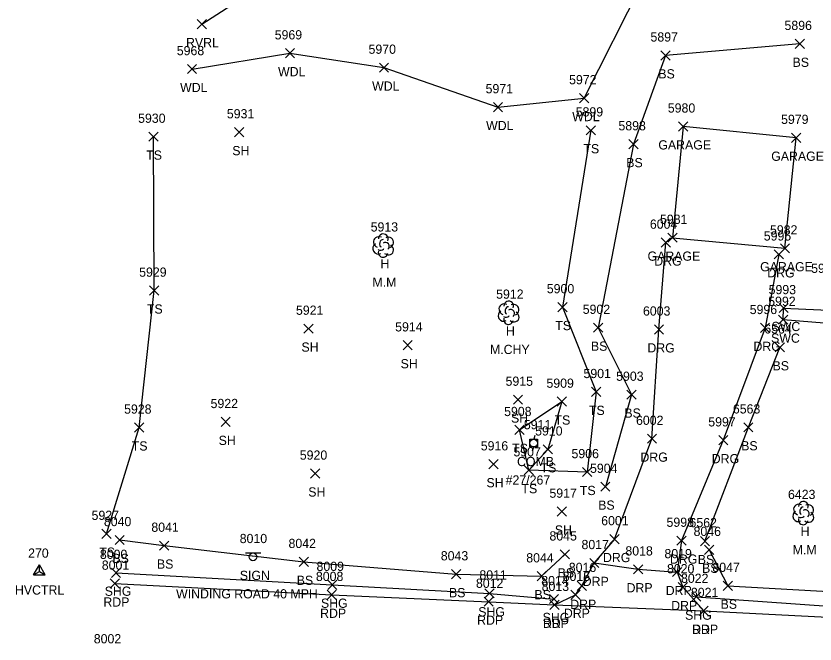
# Model space of a CAD drawing. Extents: x 1588028 to 1589597, y 137576 to 138176.
# Drawn here: x 1588400.7 to 1588574.1, y 137910.1 to 138046.3 of the extents above; entities that cross this region are included whole.
import ezdxf

# ---------------------------------------------------------------- set-up
doc = ezdxf.new("R2010")
doc.units = 0
for name, color, linetype in [('C_A', 7, 'Continuous'), ('C_I', 7, 'Continuous'), ('CPSM', 7, 'Continuous'), ('L_A', 7, 'Continuous'), ('L_C', 7, 'Continuous'), ('L_I', 7, 'Continuous'), ('L_TIC', 7, 'Continuous'), ('LAWA', 7, 'Continuous'), ('LAWE', 7, 'Continuous'), ('LBC', 7, 'Continuous'), ('LELB', 7, 'Continuous'), ('LTD', 7, 'Continuous'), ('P_A', 7, 'Continuous'), ('P_I', 7, 'Continuous'), ('P_TIC', 7, 'Continuous'), ('PET', 7, 'Continuous'), ('PSU', 7, 'Continuous'), ('R_A', 7, 'Continuous'), ('R_I', 7, 'Continuous'), ('R_TIC', 7, 'Continuous'), ('RDG', 7, 'Continuous'), ('RDP', 7, 'Continuous'), ('RSW', 7, 'Continuous'), ('S_A', 7, 'Continuous'), ('S_C', 7, 'Continuous'), ('S_I', 7, 'Continuous'), ('SSGN', 7, 'Continuous'), ('U_A', 7, 'Continuous'), ('U_C', 7, 'Continuous'), ('U_I', 7, 'Continuous'), ('UP', 7, 'Continuous')]:
    doc.layers.add(name, color=color, linetype=linetype)

msp = doc.modelspace()

# ---------------------------------------------------------------- linework, layer by layer
at = {"layer": 'CPSM'}
for p, q in [((1588404.52, 137925.06), (1588405.77, 137927.22)), ((1588407.02, 137925.06), (1588405.77, 137927.22)), ((1588405.77, 137925.78), (1588405.77, 137927.22)), ((1588404.52, 137925.06), (1588405.77, 137925.78)), ((1588404.52, 137925.06), (1588407.02, 137925.06)), ((1588405.77, 137925.78), (1588405.77, 137925.78)), ((1588405.77, 137925.78), (1588407.02, 137925.06))]:
    msp.add_line(p, q, dxfattribs=at)
at = {"layer": 'L_TIC'}
for points in [[(1588440.02, 138043.54), (1588442.02, 138045.54)], [(1588442.02, 138043.54), (1588440.02, 138045.54)], [(1588569.78, 138039.27), (1588571.78, 138041.27)], [(1588571.78, 138039.27), (1588569.78, 138041.27)], [(1588459.15, 138037.23), (1588461.15, 138039.23)], [(1588461.15, 138037.23), (1588459.15, 138039.23)], [(1588540.65, 138036.76), (1588542.65, 138038.76)], [(1588542.65, 138036.76), (1588540.65, 138038.76)], [(1588437.89, 138033.8), (1588439.89, 138035.8)], [(1588439.89, 138033.8), (1588437.89, 138035.8)], [(1588479.55, 138034.11), (1588481.55, 138036.11)], [(1588481.55, 138034.11), (1588479.55, 138036.11)], [(1588522.98, 138027.49), (1588524.98, 138029.49)], [(1588524.98, 138027.49), (1588522.98, 138029.49)], [(1588504.29, 138025.54), (1588506.29, 138027.54)], [(1588506.29, 138025.54), (1588504.29, 138027.54)], [(1588544.49, 138021.35), (1588546.49, 138023.35)], [(1588546.49, 138021.35), (1588544.49, 138023.35)], [(1588448.14, 138020.1), (1588450.14, 138022.1)], [(1588450.14, 138020.1), (1588448.14, 138022.1)], [(1588524.43, 138020.51), (1588526.43, 138022.51)], [(1588526.43, 138020.51), (1588524.43, 138022.51)], [(1588429.54, 138019.13), (1588431.54, 138021.13)], [(1588431.54, 138019.13), (1588429.54, 138021.13)], [(1588533.69, 138017.5), (1588535.69, 138019.5)], [(1588535.69, 138017.5), (1588533.69, 138019.5)], [(1588568.99, 138018.89), (1588570.99, 138020.89)], [(1588570.99, 138018.89), (1588568.99, 138020.89)], [(1588542.15, 137997.21), (1588544.15, 137999.21)], [(1588544.15, 137997.21), (1588542.15, 137999.21)], [(1588566.58, 137994.91), (1588568.58, 137996.91)], [(1588568.58, 137994.91), (1588566.58, 137996.91)], [(1588429.69, 137985.74), (1588431.69, 137987.74)], [(1588431.69, 137985.74), (1588429.69, 137987.74)], [(1588518.31, 137982.15), (1588520.31, 137984.15)], [(1588520.31, 137982.15), (1588518.31, 137984.15)], [(1588526.02, 137977.68), (1588528.02, 137979.68)], [(1588528.02, 137977.68), (1588526.02, 137979.68)], [(1588463.15, 137977.48), (1588465.15, 137979.48)], [(1588465.15, 137977.48), (1588463.15, 137979.48)], [(1588484.68, 137973.87), (1588486.68, 137975.87)], [(1588486.68, 137973.87), (1588484.68, 137975.87)], [(1588565.44, 137973.42), (1588567.44, 137975.42)], [(1588567.44, 137973.42), (1588565.44, 137975.42)], [(1588525.62, 137963.75), (1588527.62, 137965.75)], [(1588527.62, 137963.75), (1588525.62, 137965.75)], [(1588508.63, 137962.08), (1588510.63, 137964.08)], [(1588510.63, 137962.08), (1588508.63, 137964.08)], [(1588533.28, 137963.16), (1588535.28, 137965.16)], [(1588535.28, 137963.16), (1588533.28, 137965.16)], [(1588518.16, 137961.65), (1588520.16, 137963.65)], [(1588520.16, 137961.65), (1588518.16, 137963.65)], [(1588445.18, 137957.24), (1588447.18, 137959.24)], [(1588447.18, 137957.24), (1588445.18, 137959.24)], [(1588426.41, 137956.03), (1588428.41, 137958.03)], [(1588428.41, 137956.03), (1588426.41, 137958.03)], [(1588508.96, 137955.51), (1588510.96, 137957.51)], [(1588510.96, 137955.51), (1588508.96, 137957.51)], [(1588558.63, 137956.07), (1588560.63, 137958.07)], [(1588560.63, 137956.07), (1588558.63, 137958.07)], [(1588515.13, 137951.29), (1588517.13, 137953.29)], [(1588517.13, 137951.29), (1588515.13, 137953.29)], [(1588503.3, 137948.06), (1588505.3, 137950.06)], [(1588505.3, 137948.06), (1588503.3, 137950.06)], [(1588510.98, 137946.76), (1588512.98, 137948.76)], [(1588512.98, 137946.76), (1588510.98, 137948.76)], [(1588464.63, 137946.05), (1588466.63, 137948.05)], [(1588466.63, 137946.05), (1588464.63, 137948.05)], [(1588523.65, 137946.37), (1588525.65, 137948.37)], [(1588525.65, 137946.37), (1588523.65, 137948.37)], [(1588527.59, 137943.19), (1588529.59, 137945.19)], [(1588529.59, 137943.19), (1588527.59, 137945.19)], [(1588518.14, 137937.79), (1588520.14, 137939.79)], [(1588520.14, 137937.79), (1588518.14, 137939.79)], [(1588419.35, 137932.98), (1588421.35, 137934.98)], [(1588421.35, 137932.98), (1588419.35, 137934.98)], [(1588422.18, 137931.63), (1588424.18, 137933.63)], [(1588424.18, 137931.63), (1588422.18, 137933.63)], [(1588549.21, 137931.39), (1588551.21, 137933.39)], [(1588551.21, 137931.39), (1588549.21, 137933.39)], [(1588431.84, 137930.4), (1588433.84, 137932.4)], [(1588433.84, 137930.4), (1588431.84, 137932.4)], [(1588550.14, 137929.49), (1588552.14, 137931.49)], [(1588552.14, 137929.49), (1588550.14, 137931.49)], [(1588518.79, 137928.51), (1588520.79, 137930.51)], [(1588520.79, 137928.51), (1588518.79, 137930.51)], [(1588462.17, 137926.88), (1588464.17, 137928.88)], [(1588464.17, 137926.88), (1588462.17, 137928.88)], [(1588495.22, 137924.2), (1588497.22, 137926.2)], [(1588497.22, 137924.2), (1588495.22, 137926.2)], [(1588513.77, 137923.76), (1588515.77, 137925.76)], [(1588515.77, 137923.76), (1588513.77, 137925.76)], [(1588554.16, 137921.7), (1588556.16, 137923.7)], [(1588556.16, 137921.7), (1588554.16, 137923.7)]]:
    msp.add_lwpolyline(points, dxfattribs=at)
at = {"layer": 'LAWA'}
msp.add_lwpolyline([(1588438.89, 138034.8), (1588460.15, 138038.23), (1588480.55, 138035.11), (1588505.29, 138026.54), (1588523.98, 138028.49), (1588536.66, 138053.55), (1588553.84, 138097.83), (1588585.17, 138100.47), (1588614.56, 138103.49), (1588645.11, 138105.26), (1588662.06, 138103.96), (1588684.62, 138095.19), (1588717.93, 138069.71), (1588741.65, 138047.62), (1588762.05, 138028.09), (1588788.28, 138004.54)], dxfattribs=at)
at = {"layer": 'LAWE'}
msp.add_lwpolyline([(1588441.02, 138044.54), (1588465.05, 138060.11), (1588492.43, 138083.39), (1588521.86, 138113.88), (1588530.72, 138143.54), (1588545.57, 138151.23), (1588554.85, 138142.99), (1588577.1, 138115.96), (1588614.25, 138110.98), (1588643.88, 138111.05), (1588664.41, 138106.89), (1588688.53, 138102.18), (1588718.75, 138082.48), (1588743.28, 138056.23), (1588764.53, 138038.44), (1588797.04, 138013.98), (1588814.47, 138001.04), (1588852.47, 137959.37), (1588883.95, 137928.09), (1588897.47, 137912.79), (1588913.44, 137894.45), (1588920.69, 137884.16), (1588921.99, 137878.45)], dxfattribs=at)
at = {"layer": 'LBC'}
for points in [[(1588569.99, 138019.89), (1588545.49, 138022.35), (1588543.15, 137998.21), (1588567.58, 137995.91)], [(1588567.58, 137995.91), (1588569.99, 138019.89)]]:
    msp.add_lwpolyline(points, dxfattribs=at)
at = {"layer": 'LELB'}
for points in [[(1588570.78, 138040.27), (1588541.65, 138037.76), (1588534.69, 138018.5), (1588527.02, 137978.68), (1588534.28, 137964.16), (1588528.59, 137944.19)], [(1588525.43, 138021.51), (1588519.31, 137983.15), (1588526.62, 137964.75), (1588524.65, 137947.37), (1588511.98, 137947.76), (1588509.96, 137956.51), (1588519.16, 137962.65), (1588516.13, 137952.29)], [(1588420.35, 137933.98), (1588427.41, 137957.03), (1588430.69, 137986.74), (1588430.54, 138020.13)], [(1588550.21, 137932.39), (1588559.63, 137957.07), (1588566.44, 137974.42)], [(1588516.13, 137952.29), (1588511.98, 137947.76)], [(1588423.18, 137932.63), (1588432.84, 137931.4), (1588463.17, 137927.88), (1588496.22, 137925.2), (1588514.77, 137924.76), (1588519.79, 137929.51)], [(1588551.14, 137930.49), (1588555.16, 137922.7), (1588594.96, 137920.46), (1588624.61, 137918.77), (1588663.54, 137916.63), (1588704.8, 137915.23), (1588747.54, 137910.9), (1588783.34, 137911.62)]]:
    msp.add_lwpolyline(points, dxfattribs=at)
at = {"layer": 'LTD'}
for p, q in [((1588480.35, 137996.55), (1588480.35, 137996.55)), ((1588480.35, 137996.55), (1588480.35, 137996.55)), ((1588507.58, 137981.97), (1588507.58, 137981.97)), ((1588507.58, 137981.97), (1588507.58, 137981.97)), ((1588571.54, 137938.51), (1588571.54, 137938.51)), ((1588571.54, 137938.51), (1588571.54, 137938.51))]:
    msp.add_line(p, q, dxfattribs=at)
for centre in [(1588480.4, 137997.98), (1588507.63, 137983.4), (1588571.58, 137939.94)]:
    msp.add_arc(centre, 1.05, 335.5272, 180.9563, dxfattribs=at)
for centre, major_axis, ratio, start_param, end_param in [((1588479.56, 137997.21), (1.21, -0.51), 0.895232, 1.570796, 4.712389), ((1588480.14, 137997), (-0.208, -0.792), 0.645439, 3.141593, 6.283185), ((1588480.85, 137996.38), (-0.5, 0.667), 0.989748, 3.141593, 6.283185), ((1588481.39, 137997.13), (-1.14, -0.48), 0.949671, 1.570796, 4.712389), ((1588479.27, 137995.84), (0.58, -1.04), 0.959034, 3.141593, 6.283185), ((1588480.35, 137995.05), (0.26, 1.06), 0.942809, 1.570796, 4.712389), ((1588479.89, 137995.8), (-0.625, -0.083), 0.423636, 0, 3.141593), ((1588481.35, 137995.71), (-1.09, 0.79), 0.841452, 1.570796, 4.712389), ((1588506.79, 137982.64), (1.21, -0.51), 0.895232, 1.570796, 4.712389), ((1588507.37, 137982.43), (-0.208, -0.792), 0.645439, 3.141593, 6.283185), ((1588508.62, 137982.55), (-1.14, -0.48), 0.949671, 1.570796, 4.712389), ((1588506.5, 137981.26), (0.58, -1.04), 0.959034, 3.141593, 6.283185), ((1588508.08, 137981.8), (-0.5, 0.667), 0.989748, 3.141593, 6.283185), ((1588508.58, 137981.14), (-1.09, 0.79), 0.841452, 1.570796, 4.712389), ((1588507.58, 137980.47), (0.26, 1.06), 0.942809, 1.570796, 4.712389), ((1588507.12, 137981.22), (-0.625, -0.083), 0.423636, 0, 3.141593), ((1588570.74, 137939.18), (1.21, -0.51), 0.895232, 1.570796, 4.712389), ((1588571.33, 137938.97), (-0.208, -0.792), 0.645439, 3.141593, 6.283185), ((1588572.58, 137939.09), (-1.14, -0.48), 0.949671, 1.570796, 4.712389), ((1588570.45, 137937.8), (0.58, -1.04), 0.959034, 3.141593, 6.283185), ((1588572.04, 137938.34), (-0.5, 0.667), 0.989748, 3.141593, 6.283185), ((1588572.54, 137937.68), (-1.09, 0.79), 0.841452, 1.570796, 4.712389), ((1588571.54, 137937.01), (0.26, 1.06), 0.942809, 1.570796, 4.712389), ((1588571.08, 137937.76), (-0.625, -0.083), 0.423636, 0, 3.141593)]:
    msp.add_ellipse(centre, major_axis=major_axis, ratio=ratio, start_param=start_param, end_param=end_param, dxfattribs=at)
at = {"layer": 'P_TIC'}
for points in [[(1588421.4, 137924.52), (1588423.4, 137926.52)], [(1588423.4, 137924.52), (1588421.4, 137926.52)], [(1588421.16, 137922.17), (1588423.16, 137924.17)], [(1588423.16, 137922.17), (1588421.16, 137924.17)], [(1588468.34, 137921.91), (1588470.34, 137923.91)], [(1588470.34, 137921.91), (1588468.34, 137923.91)], [(1588468.2, 137919.73), (1588470.2, 137921.73)], [(1588470.2, 137919.73), (1588468.2, 137921.73)], [(1588502.46, 137920.05), (1588504.46, 137922.05)], [(1588504.46, 137920.05), (1588502.46, 137922.05)], [(1588516.45, 137918.82), (1588518.45, 137920.82)], [(1588518.45, 137918.82), (1588516.45, 137920.82)], [(1588547.35, 137919.32), (1588549.35, 137921.32)], [(1588549.35, 137919.32), (1588547.35, 137921.32)], [(1588502.28, 137918.24), (1588504.28, 137920.24)], [(1588504.28, 137918.24), (1588502.28, 137920.24)], [(1588516.55, 137917.56), (1588518.55, 137919.56)], [(1588518.55, 137917.56), (1588516.55, 137919.56)], [(1588548.94, 137916.25), (1588550.94, 137918.25)], [(1588550.94, 137916.25), (1588548.94, 137918.25)]]:
    msp.add_lwpolyline(points, dxfattribs=at)
at = {"layer": 'PET'}
msp.add_lwpolyline([(1588422.16, 137923.17), (1588469.2, 137920.73), (1588503.28, 137919.24), (1588517.55, 137918.56), (1588549.94, 137917.25), (1588592.35, 137915.11), (1588643.26, 137911.75), (1588663.5, 137910.85), (1588704.32, 137908.35), (1588747.19, 137904.38), (1588787.69, 137899.08), (1588825.32, 137893.63), (1588865.15, 137887.82), (1588905.82, 137880.77), (1588917.24, 137863.85), (1588927.99, 137847.51)], dxfattribs=at)
at = {"layer": 'PSU'}
for points in [[(1588422.4, 137925.52), (1588469.34, 137922.91), (1588503.46, 137921.05), (1588517.45, 137919.82)], [(1588548.35, 137920.32), (1588592.38, 137917.18), (1588643.62, 137914.8), (1588663.46, 137913.57), (1588704.41, 137911.28), (1588747.22, 137907.04), (1588788.55, 137903.91), (1588803.43, 137901.36)]]:
    msp.add_lwpolyline(points, dxfattribs=at)
at = {"layer": 'R_TIC'}
for points in [[(1588540.72, 137996.15), (1588542.72, 137998.15)], [(1588542.72, 137996.15), (1588540.72, 137998.15)], [(1588565.23, 137993.59), (1588567.23, 137995.59)], [(1588567.23, 137993.59), (1588565.23, 137995.59)], [(1588566.29, 137981.95), (1588568.29, 137983.95)], [(1588568.29, 137981.95), (1588566.29, 137983.95)], [(1588566.2, 137979.42), (1588568.2, 137981.42)], [(1588568.2, 137979.42), (1588566.2, 137981.42)], [(1588562.24, 137977.64), (1588564.24, 137979.64)], [(1588564.24, 137977.64), (1588562.24, 137979.64)], [(1588539.23, 137977.31), (1588541.23, 137979.31)], [(1588541.23, 137977.31), (1588539.23, 137979.31)], [(1588537.71, 137953.6), (1588539.71, 137955.6)], [(1588539.71, 137953.6), (1588537.71, 137955.6)], [(1588553.19, 137953.26), (1588555.19, 137955.26)], [(1588555.19, 137953.26), (1588553.19, 137955.26)], [(1588529.59, 137931.82), (1588531.59, 137933.82)], [(1588531.59, 137931.82), (1588529.59, 137933.82)], [(1588544.13, 137931.48), (1588546.13, 137933.48)], [(1588546.13, 137931.48), (1588544.13, 137933.48)], [(1588525.19, 137926.64), (1588527.19, 137928.64)], [(1588527.19, 137926.64), (1588525.19, 137928.64)], [(1588534.71, 137925.26), (1588536.71, 137927.26)], [(1588536.71, 137925.26), (1588534.71, 137927.26)], [(1588543.2, 137924.67), (1588545.2, 137926.67)], [(1588545.2, 137924.67), (1588543.2, 137926.67)], [(1588522.49, 137921.68), (1588524.49, 137923.68)], [(1588524.49, 137921.68), (1588522.49, 137923.68)], [(1588544.4, 137921.4), (1588546.4, 137923.4)], [(1588546.4, 137921.4), (1588544.4, 137923.4)], [(1588521.1, 137919.73), (1588523.1, 137921.73)], [(1588523.1, 137919.73), (1588521.1, 137921.73)], [(1588516.55, 137917.56), (1588518.55, 137919.56)], [(1588518.55, 137917.56), (1588516.55, 137919.56)], [(1588548.94, 137916.25), (1588550.94, 137918.25)], [(1588550.94, 137916.25), (1588548.94, 137918.25)]]:
    msp.add_lwpolyline(points, dxfattribs=at)
at = {"layer": 'RDG'}
for points in [[(1588530.59, 137932.82), (1588538.71, 137954.6), (1588540.23, 137978.31), (1588541.72, 137997.15)], [(1588566.23, 137994.59), (1588563.24, 137978.64), (1588554.19, 137954.26), (1588545.13, 137932.48)], [(1588530.59, 137932.82), (1588526.19, 137927.64)], [(1588545.13, 137932.48), (1588544.2, 137925.67)]]:
    msp.add_lwpolyline(points, dxfattribs=at)
at = {"layer": 'RDP'}
msp.add_lwpolyline([(1588517.55, 137918.56), (1588522.1, 137920.73), (1588523.49, 137922.68), (1588526.19, 137927.64), (1588535.71, 137926.26), (1588544.2, 137925.67), (1588545.4, 137922.4), (1588549.94, 137917.25)], dxfattribs=at)
at = {"layer": 'RSW'}
msp.add_lwpolyline([(1588594.74, 137981.97), (1588594.78, 137978.17), (1588567.2, 137980.42), (1588567.29, 137982.95), (1588590, 137981.88)], dxfattribs=at)
at = {"layer": 'SSGN'}
for p, q in [((1588450.47, 137929.81), (1588453.81, 137929.81)), ((1588452.12, 137928.97), (1588452.12, 137928.97))]:
    msp.add_line(p, q, dxfattribs=at)
msp.add_circle((1588452.12, 137928.97), 0.833, dxfattribs=at)
at = {"layer": 'UP'}
for p, q in [((1588513.29, 137955.32), (1588513.04, 137954.48)), ((1588512.2, 137952.82), (1588512.2, 137954.48)), ((1588512.2, 137954.48), (1588513.87, 137954.48)), ((1588513.04, 137953.65), (1588513.04, 137953.65)), ((1588513.87, 137954.48), (1588513.87, 137952.82)), ((1588513.87, 137952.82), (1588512.2, 137952.82)), ((1588512.79, 137951.98), (1588513.04, 137952.82))]:
    msp.add_line(p, q, dxfattribs=at)
msp.add_circle((1588513.04, 137953.65), 0.833, dxfattribs=at)

# ---------------------------------------------------------------- texts
at = {"layer": 'C_A'}
msp.add_text('HVCTRL', height=2, dxfattribs=at).set_placement((1588400.46, 137920.78))
at = {"layer": 'C_I'}
msp.add_text('270', height=2, dxfattribs=at).set_placement((1588403.32, 137928.78))
at = {"layer": 'L_A'}
for s, p in [('RVRL', (1588437.59, 138039.54)), ('BS', (1588569.22, 138035.27)), ('WDL', (1588457.56, 138033.23)), ('BS', (1588540.09, 138032.76)), ('WDL', (1588436.3, 138029.8)), ('WDL', (1588477.97, 138030.11)), ('WDL', (1588521.4, 138023.49)), ('WDL', (1588502.71, 138021.54)), ('SH', (1588447.63, 138016.1)), ('TS', (1588523.84, 138016.51)), ('GARAGE', (1588540.09, 138017.35)), ('TS', (1588428.95, 138015.13)), ('GARAGE', (1588564.59, 138014.89)), ('BS', (1588533.13, 138013.5)), ('GARAGE', (1588537.75, 137993.21)), ('H', (1588479.79, 137991.55)), ('GARAGE', (1588562.18, 137990.91)), ('TS', (1588429.1, 137981.74)), ('TS', (1588517.72, 137978.15)), ('H', (1588507.02, 137976.97)), ('SH', (1588462.64, 137973.48)), ('BS', (1588525.46, 137973.68)), ('SH', (1588484.16, 137969.87)), ('BS', (1588564.88, 137969.42)), ('TS', (1588525.03, 137959.75)), ('BS', (1588532.72, 137959.16)), ('SH', (1588508.12, 137958.08)), ('TS', (1588517.57, 137957.65)), ('TS', (1588425.82, 137952.03)), ('SH', (1588444.67, 137953.24)), ('BS', (1588558.07, 137952.07)), ('TS', (1588508.37, 137951.51)), ('TS', (1588514.54, 137947.29)), ('SH', (1588502.79, 137944.06)), ('SH', (1588464.12, 137942.05)), ('TS', (1588510.39, 137942.76)), ('TS', (1588523.06, 137942.37)), ('BS', (1588527.04, 137939.19)), ('SH', (1588517.63, 137933.79)), ('H', (1588570.97, 137933.51)), ('TS', (1588418.76, 137928.98)), ('BS', (1588421.62, 137927.63)), ('BS', (1588548.65, 137927.39)), ('BS', (1588431.28, 137926.4)), ('BS', (1588518.24, 137924.51)), ('BS', (1588549.58, 137925.49)), ('BS', (1588461.61, 137922.88)), ('BS', (1588494.66, 137920.2)), ('BS', (1588513.21, 137919.76)), ('BS', (1588553.6, 137917.7))]:
    msp.add_text(s, height=2, dxfattribs=at).set_placement(p)
at = {"layer": 'L_C'}
for s, p in [('M.M', (1588478.05, 137987.55)), ('M.CHY', (1588503.55, 137972.97)), ('M.M', (1588569.24, 137929.51))]:
    msp.add_text(s, height=2, dxfattribs=at).set_placement(p)
at = {"layer": 'L_I'}
for s, p in [('5896', (1588567.47, 138043.27)), ('5969', (1588456.83, 138041.23)), ('5897', (1588538.39, 138040.76)), ('5968', (1588435.58, 138037.8)), ('5970', (1588477.2, 138038.11)), ('5972', (1588520.72, 138031.49)), ('5971', (1588502.6, 138029.54)), ('5899', (1588522.16, 138024.51)), ('5980', (1588542.15, 138025.35)), ('5930', (1588427.19, 138023.13)), ('5931', (1588446.45, 138024.1)), ('5979', (1588566.73, 138022.89)), ('5898', (1588531.43, 138021.5)), ('5981', (1588540.45, 138001.21)), ('5913', (1588477.66, 137999.55)), ('5982', (1588564.32, 137998.91)), ('5929', (1588427.42, 137989.74)), ('5984', (1588573.26, 137990.57)), ('5912', (1588504.89, 137984.97)), ('5900', (1588515.89, 137986.15)), ('5921', (1588461.45, 137981.48)), ('5902', (1588523.68, 137981.68)), ('5914', (1588482.98, 137977.87)), ('6564', (1588563.09, 137977.42)), ('5901', (1588523.85, 137967.75)), ('5903', (1588530.94, 137967.16)), ('5915', (1588506.94, 137966.08)), ('5909', (1588515.81, 137965.65)), ('5922', (1588442.92, 137961.24)), ('5928', (1588424.15, 137960.03)), ('5908', (1588506.62, 137959.51)), ('6563', (1588556.27, 137960.07)), ('5910', (1588513.35, 137955.29)), ('5916', (1588501.55, 137952.06)), ('5920', (1588462.28, 137950.05)), ('5907', (1588508.64, 137950.76)), ('5906', (1588521.25, 137950.37)), ('5904', (1588525.26, 137947.19)), ('5917', (1588516.45, 137941.79)), ('6423', (1588568.23, 137941.51)), ('5927', (1588417.09, 137936.98)), ('8040', (1588419.76, 137935.63)), ('8041', (1588430.06, 137934.4)), ('6562', (1588546.86, 137935.39)), ('8045', (1588516.46, 137932.51)), ('8046', (1588547.74, 137933.49)), ('8042', (1588459.83, 137930.88)), ('8043', (1588492.88, 137928.2)), ('8044', (1588511.43, 137927.76)), ('8047', (1588551.82, 137925.7))]:
    msp.add_text(s, height=2, dxfattribs=at).set_placement(p)
at = {"layer": 'P_A'}
for s, p in [('SHG', (1588419.94, 137920.52)), ('RDP', (1588419.65, 137918.17)), ('SHG', (1588466.87, 137917.91)), ('RDP', (1588466.69, 137915.73)), ('SHG', (1588501, 137916.05)), ('SHG', (1588545.89, 137915.32)), ('RDP', (1588500.77, 137914.24)), ('SHG', (1588514.98, 137914.82)), ('RDP', (1588515.03, 137913.56)), ('RDP', (1588547.42, 137912.25))]:
    msp.add_text(s, height=2, dxfattribs=at).set_placement(p)
at = {"layer": 'P_I'}
for s, p in [('8000', (1588418.9, 137928.52)), ('8001', (1588419.31, 137926.17)), ('8009', (1588465.91, 137925.91)), ('8011', (1588501.26, 137924.05)), ('8008', (1588465.78, 137923.73)), ('8012', (1588500.51, 137922.24)), ('8014', (1588514.68, 137922.82)), ('8022', (1588545.01, 137923.32)), ('8013', (1588514.77, 137921.56)), ('8021', (1588547.16, 137920.25)), ('8002', (1588417.57, 137910.2))]:
    msp.add_text(s, height=2, dxfattribs=at).set_placement(p)
at = {"layer": 'R_A'}
for s, p in [('DRG', (1588539.21, 137992.15)), ('DRG', (1588563.72, 137989.59)), ('SWC', (1588564.65, 137977.95)), ('SWC', (1588564.56, 137975.42)), ('DRG', (1588537.71, 137973.31)), ('DRG', (1588560.73, 137973.64)), ('DRG', (1588536.2, 137949.6)), ('DRG', (1588551.68, 137949.26)), ('DRG', (1588528.08, 137927.82)), ('DRG', (1588542.62, 137927.48)), ('DRP', (1588523.68, 137922.64)), ('DRP', (1588533.2, 137921.26)), ('DRP', (1588541.69, 137920.67)), ('DRP', (1588520.97, 137917.68)), ('DRP', (1588542.88, 137917.4)), ('DRP', (1588519.59, 137915.73)), ('DRP', (1588515.03, 137913.56)), ('DRP', (1588547.42, 137912.25))]:
    msp.add_text(s, height=2, dxfattribs=at).set_placement(p)
at = {"layer": 'R_I'}
for s, p in [('6004', (1588538.26, 138000.15)), ('5995', (1588562.97, 137997.59)), ('5993', (1588564.03, 137985.95)), ('5992', (1588563.94, 137983.42)), ('6003', (1588536.76, 137981.31)), ('5996', (1588559.92, 137981.64)), ('6002', (1588535.25, 137957.6)), ('5997', (1588550.93, 137957.26)), ('6001', (1588527.69, 137935.82)), ('5998', (1588541.87, 137935.48)), ('8017', (1588523.42, 137930.64)), ('8018', (1588532.94, 137929.26)), ('8019', (1588541.42, 137928.67)), ('8016', (1588520.66, 137925.68)), ('8020', (1588541.97, 137925.4)), ('8015', (1588519.33, 137923.73)), ('8013', (1588514.77, 137921.56)), ('8021', (1588547.16, 137920.25))]:
    msp.add_text(s, height=2, dxfattribs=at).set_placement(p)
at = {"layer": 'S_A'}
msp.add_text('SIGN', height=2, dxfattribs=at).set_placement((1588449.26, 137923.95))
at = {"layer": 'S_C'}
msp.add_text('WINDING ROAD 40 MPH', height=2, dxfattribs=at).set_placement((1588435.43, 137919.95))
at = {"layer": 'S_I'}
msp.add_text('8010', height=2, dxfattribs=at).set_placement((1588449.24, 137931.95))
at = {"layer": 'U_A'}
msp.add_text('COMB', height=2, dxfattribs=at).set_placement((1588509.42, 137948.65))
at = {"layer": 'U_C'}
msp.add_text('#27/267', height=2, dxfattribs=at).set_placement((1588506.96, 137944.65))
at = {"layer": 'U_I'}
msp.add_text('5911', height=2, dxfattribs=at).set_placement((1588510.91, 137956.65))

doc.saveas('drawing.dxf')
